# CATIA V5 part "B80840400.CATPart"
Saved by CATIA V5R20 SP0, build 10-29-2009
Part number: B80840400
Revision: 3
Definition: design
Nomenclature: B80840400
Source: made
Description: NOT SPECIFIED
Bounding box of the stored display mesh (mm): x -22.5 to 22.5, y -22.5 to 22.5, z 0 to 400
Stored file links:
  C:\Users\Raffaele\Desktop\3D X SITO CF\BOLEX\4-PILLAR REF 808\B80840400.CATPart
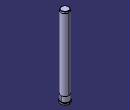
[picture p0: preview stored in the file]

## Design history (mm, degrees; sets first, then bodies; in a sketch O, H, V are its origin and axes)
Body1 "MANIFOLD_SOLID_BREP #450" (main body)
  Solid1: solid without history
